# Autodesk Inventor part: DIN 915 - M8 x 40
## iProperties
Created: 2006-02
Part Number: DIN 915 - M8 x 40
Material: Steel, Mild
Description: Hexagon Socket Set Screw
Document SubType Name: Modeling
Standard: DIN 915
Designer: Andy Moles
Standards Organization: DIN
Language: en-US
Size Designation: M8 x 40
Categories: <MemberInstance><Categories><Category DisplayName="Fasteners" InternalName="e4da775c-781d-43d5-af7c-5136215cf5a6" Mnemonic="FSTN"><Category DisplayName="Bolts"
Density: 1 g/cm^3
Author: Andy Moles
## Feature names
1. Body [Revolution]
2. Chamfer1
3. Slot [Extrusion]
4. Chamfer2
